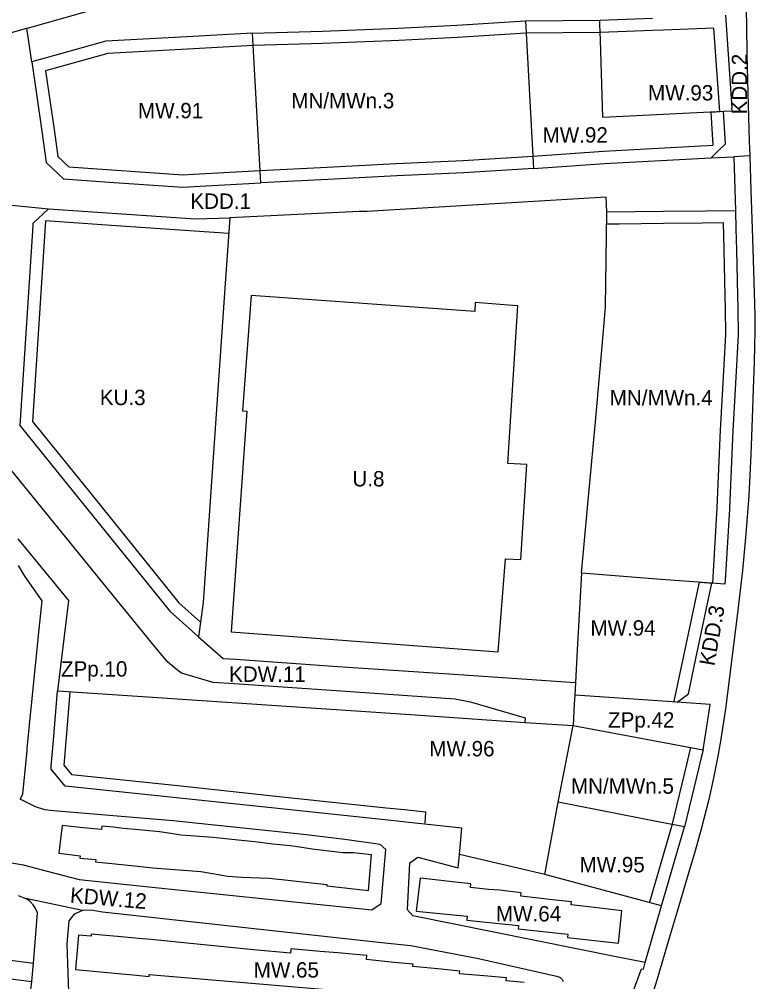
# Model space of a CAD drawing. Extents: x 7424434 to 7425898, y 5541432 to 5542659.
# Drawn here: x 7425584.1 to 7425823, y 5542027 to 5542339.7 of the extents above; entities that cross this region are included whole.
import ezdxf

# ---------------------------------------------------------------- set-up
doc = ezdxf.new("R2010")
doc.units = 0
for name, color, linetype in [('Default', 7, 'Continuous'), ('linie rozgraniczające', 7, 'Continuous'), ('nieprzekraczalne linie zabudowy', 7, 'Continuous'), ('obowiazujace linie zabudowy', 7, 'Continuous'), ('przeznaczenia terenów', 7, 'Continuous')]:
    doc.layers.add(name, color=color, linetype=linetype)

# ---------------------------------------------------------------- blocks, each defined once
blk = doc.blocks.new('POINT_DISPLAY')
at = {"layer": 'Default'}
blk.add_line((0, 0), (0, 0), dxfattribs=at)

msp = doc.modelspace()

# ---------------------------------------------------------------- linework, layer by layer
at = {"layer": 'linie rozgraniczające'}
for p, q in [((7425820.13, 5542347.32), (7425820.33, 5542337.89)), ((7425586.82, 5542336.84), (7425612.05, 5542343.91)), ((7425813.48, 5542341), (7425815.61, 5542310.78)), ((7425707.19, 5542336.79), (7425726.25, 5542337.79)), ((7425726.25, 5542337.79), (7425748.57, 5542339.2)), ((7425748.57, 5542339.2), (7425772.68, 5542339.36)), ((7425748.57, 5542339.2), (7425751.17, 5542291.2)), ((7425772.68, 5542339.36), (7425789.77, 5542340.05)), ((7425772.72, 5542338.14), (7425772.68, 5542339.36)), ((7425772.87, 5542332.92), (7425772.72, 5542338.14)), ((7425820.33, 5542337.89), (7425820.46, 5542328.05)), ((7425564.85, 5542330.75), (7425586.62, 5542336.78)), ((7425586.62, 5542336.78), (7425586.82, 5542336.84)), ((7425588.21, 5542325.83), (7425586.62, 5542336.78)), ((7425659.91, 5542335.18), (7425638.59, 5542334.02)), ((7425659.91, 5542335.18), (7425682.59, 5542335.83)), ((7425660.75, 5542319.63), (7425659.91, 5542335.18)), ((7425682.59, 5542335.83), (7425704.64, 5542336.69)), ((7425704.64, 5542336.69), (7425707.19, 5542336.79)), ((7425612.29, 5542332.58), (7425588.21, 5542325.83)), ((7425638.59, 5542334.02), (7425612.29, 5542332.58)), ((7425773.62, 5542307.87), (7425772.87, 5542332.92)), ((7425588.21, 5542325.83), (7425591.48, 5542303.35)), ((7425820.46, 5542328.05), (7425820.72, 5542315.79)), ((7425662.55, 5542286.57), (7425660.75, 5542319.63)), ((7425820.72, 5542315.79), (7425821.24, 5542300.09)), ((7425773.62, 5542307.87), (7425812.82, 5542309.79)), ((7425812.82, 5542309.79), (7425815.67, 5542309.93)), ((7425813.48, 5542299.23), (7425812.82, 5542309.79)), ((7425815.67, 5542309.93), (7425815.61, 5542310.78)), ((7425591.48, 5542303.35), (7425592.87, 5542293.15)), ((7425821.24, 5542300.09), (7425821.39, 5542295.38)), ((7425810.87, 5542296.71), (7425813.48, 5542299.23)), ((7425774.17, 5542292.81), (7425808.75, 5542294.66)), ((7425808.75, 5542294.66), (7425816.17, 5542295.05)), ((7425808.75, 5542294.66), (7425808.8, 5542294.71)), ((7425808.8, 5542294.71), (7425810.87, 5542296.71)), ((7425821.39, 5542295.38), (7425816.17, 5542295.05)), ((7425816.17, 5542295.05), (7425816.77, 5542277.58)), ((7425821.39, 5542295.38), (7425821.76, 5542284.09)), ((7425592.87, 5542293.15), (7425598.54, 5542287.85)), ((7425751.17, 5542291.2), (7425728.48, 5542289.81)), ((7425751.17, 5542291.2), (7425774.17, 5542292.81)), ((7425598.54, 5542287.85), (7425614.94, 5542286.72)), ((7425684.3, 5542287.64), (7425662.55, 5542286.57)), ((7425706.78, 5542288.82), (7425684.3, 5542287.64)), ((7425728.48, 5542289.81), (7425706.78, 5542288.82)), ((7425614.94, 5542286.72), (7425637.29, 5542285.18)), ((7425637.29, 5542285.18), (7425640.94, 5542285.38)), ((7425640.94, 5542285.38), (7425662.55, 5542286.57)), ((7425774.74, 5542281.86), (7425697.06, 5542277.29)), ((7425774.98, 5542277.14), (7425774.74, 5542281.86)), ((7425821.76, 5542284.09), (7425822.16, 5542271.74)), ((7425577.28, 5542279.74), (7425593.66, 5542278.16)), ((7425593.66, 5542278.16), (7425588.52, 5542273.39)), ((7425593.66, 5542278.16), (7425614.29, 5542276.74)), ((7425614.29, 5542276.74), (7425641.42, 5542274.87)), ((7425641.42, 5542274.87), (7425652.53, 5542275.14)), ((7425652.53, 5542275.14), (7425650.93, 5542252.36)), ((7425694.51, 5542277.23), (7425652.53, 5542275.14)), ((7425697.06, 5542277.29), (7425694.51, 5542277.23)), ((7425774.56, 5542246.29), (7425774.98, 5542277.14)), ((7425774.98, 5542277.14), (7425793.34, 5542277.33)), ((7425793.34, 5542277.33), (7425807.13, 5542277.48)), ((7425807.13, 5542277.48), (7425816.77, 5542277.58)), ((7425816.77, 5542277.58), (7425816.89, 5542271.62)), ((7425588.5, 5542272.6), (7425584.37, 5542207.73)), ((7425588.52, 5542273.14), (7425588.5, 5542272.6)), ((7425588.52, 5542273.39), (7425588.52, 5542273.14)), ((7425816.89, 5542271.62), (7425817.03, 5542264.73)), ((7425822.16, 5542271.74), (7425822.61, 5542258.07)), ((7425817.03, 5542264.73), (7425817.43, 5542249.81)), ((7425822.61, 5542258.07), (7425823, 5542243.56)), ((7425650.93, 5542252.36), (7425648.25, 5542213.07)), ((7425817.43, 5542249.81), (7425817.53, 5542245.83)), ((7425773.93, 5542238.44), (7425774.56, 5542246.29)), ((7425817.53, 5542245.83), (7425817.6, 5542237.21)), ((7425823, 5542243.56), (7425823, 5542238.32)), ((7425771.36, 5542210.15), (7425773.93, 5542238.44)), ((7425823, 5542238.32), (7425822.77, 5542228.43)), ((7425817.6, 5542237.21), (7425816.94, 5542225.31)), ((7425822.77, 5542228.43), (7425822.46, 5542219.66)), ((7425816.94, 5542225.31), (7425815.87, 5542205.98)), ((7425822.46, 5542219.66), (7425822.13, 5542210.05)), ((7425648.25, 5542213.07), (7425643.82, 5542150.17)), ((7425769.1, 5542185.66), (7425771.36, 5542210.15)), ((7425822.13, 5542210.05), (7425821.72, 5542198.33)), ((7425584.37, 5542207.73), (7425603.81, 5542183.61)), ((7425815.87, 5542205.98), (7425814.78, 5542180.74)), ((7425821.72, 5542198.33), (7425821.04, 5542184.91)), ((7425613.28, 5542154.25), (7425578.96, 5542196.49)), ((7425766.75, 5542159.72), (7425769, 5542184.59)), ((7425769, 5542184.59), (7425769.1, 5542185.66)), ((7425821.04, 5542184.91), (7425820.15, 5542172.55)), ((7425603.81, 5542183.61), (7425633.03, 5542147.35)), ((7425814.76, 5542180.54), (7425813.51, 5542159.13)), ((7425814.78, 5542180.74), (7425814.76, 5542180.54)), ((7425820.15, 5542172.55), (7425819.04, 5542160.65)), ((7425583.73, 5542170.93), (7425600.13, 5542150.9)), ((7425586, 5542158.81), (7425583.91, 5542162.26)), ((7425766.75, 5542159.72), (7425765.3, 5542134.8)), ((7425792.66, 5542157.73), (7425766.75, 5542159.72)), ((7425819.04, 5542160.65), (7425817.34, 5542145.9)), ((7425591.53, 5542150.73), (7425586, 5542158.81)), ((7425809.05, 5542156.47), (7425792.66, 5542157.73)), ((7425803.89, 5542132.07), (7425809.05, 5542156.47)), ((7425813.33, 5542156.14), (7425809.05, 5542156.47)), ((7425813.51, 5542159.13), (7425813.33, 5542156.14)), ((7425627.01, 5542137.29), (7425613.28, 5542154.25)), ((7425590.6, 5542141.51), (7425591.53, 5542150.73)), ((7425600.13, 5542150.9), (7425596.58, 5542121.55)), ((7425643.82, 5542150.17), (7425642.38, 5542139.11)), ((7425633.03, 5542147.35), (7425642.38, 5542139.11)), ((7425817.34, 5542145.9), (7425813.47, 5542115.62)), ((7425586.74, 5542102.84), (7425590.6, 5542141.51)), ((7425642.38, 5542139.11), (7425650.38, 5542132.06)), ((7425632.21, 5542131.1), (7425627.01, 5542137.29)), ((7425765.3, 5542134.8), (7425764.74, 5542124.19)), ((7425634.59, 5542128.96), (7425632.21, 5542131.1)), ((7425650.38, 5542132.06), (7425654.45, 5542131.78)), ((7425654.45, 5542131.78), (7425687.59, 5542129.47)), ((7425801.44, 5542120.52), (7425803.89, 5542132.07)), ((7425636.88, 5542127.21), (7425634.59, 5542128.96)), ((7425687.59, 5542129.47), (7425726.94, 5542126.79)), ((7425647.12, 5542124.26), (7425636.88, 5542127.21)), ((7425726.94, 5542126.79), (7425764.74, 5542124.19)), ((7425653.9, 5542123.8), (7425647.12, 5542124.26)), ((7425687.04, 5542121.49), (7425653.9, 5542123.8)), ((7425764.74, 5542124.19), (7425764.52, 5542120.11)), ((7425595.24, 5542105.36), (7425596.58, 5542121.55)), ((7425596.58, 5542121.55), (7425625.77, 5542119.58)), ((7425625.77, 5542119.58), (7425711.22, 5542113.8)), ((7425725.67, 5542118.84), (7425687.04, 5542121.49)), ((7425731.17, 5542117.68), (7425725.67, 5542118.84)), ((7425764.52, 5542120.11), (7425764.36, 5542117.24)), ((7425764.52, 5542120.11), (7425764.63, 5542120.1)), ((7425797.86, 5542117.81), (7425764.63, 5542120.1)), ((7425797.86, 5542117.81), (7425801.44, 5542120.52)), ((7425748.5, 5542112.62), (7425731.17, 5542117.68)), ((7425764.36, 5542117.24), (7425763.99, 5542110.23)), ((7425808.57, 5542117.07), (7425797.86, 5542117.81)), ((7425807.88, 5542112.77), (7425808.57, 5542117.07)), ((7425813.47, 5542115.62), (7425812.68, 5542110.09)), ((7425711.22, 5542113.8), (7425748.41, 5542111.28)), ((7425748.41, 5542111.28), (7425748.5, 5542112.62)), ((7425806.2, 5542102.36), (7425807.88, 5542112.77)), ((7425759.2, 5542085.34), (7425763.99, 5542110.23)), ((7425763.99, 5542110.23), (7425802.83, 5542102.99)), ((7425812.68, 5542110.09), (7425811.9, 5542105.19)), ((7425594.55, 5542097.07), (7425595.24, 5542105.36)), ((7425802.83, 5542102.99), (7425806.2, 5542102.36)), ((7425811.9, 5542105.19), (7425810.92, 5542099.72)), ((7425585.29, 5542087.99), (7425586.67, 5542102.14)), ((7425586.67, 5542102.14), (7425586.74, 5542102.84)), ((7425806.2, 5542102.36), (7425805.5, 5542099.47)), ((7425594.47, 5542096.06), (7425594.55, 5542097.07)), ((7425804.93, 5542097.11), (7425804.7, 5542096.15)), ((7425805.5, 5542099.47), (7425804.93, 5542097.11)), ((7425810.92, 5542099.72), (7425809.53, 5542092.75)), ((7425599.07, 5542090.55), (7425594.47, 5542096.06)), ((7425804.7, 5542096.15), (7425800.15, 5542077.33)), ((7425635.22, 5542086.73), (7425599.07, 5542090.55)), ((7425809.53, 5542092.75), (7425808.08, 5542086.24)), ((7425584.47, 5542086.32), (7425585.29, 5542087.99)), ((7425589.39, 5542083.87), (7425584.47, 5542086.32)), ((7425669.06, 5542083.15), (7425635.22, 5542086.73)), ((7425754.82, 5542061.82), (7425759.2, 5542085.34)), ((7425792.2, 5542078.88), (7425759.2, 5542085.34)), ((7425808.08, 5542086.24), (7425805.64, 5542076.59)), ((7425592.41, 5542082.87), (7425589.39, 5542083.87)), ((7425595.27, 5542082.52), (7425592.41, 5542082.87)), ((7425634.13, 5542079.3), (7425595.27, 5542082.52)), ((7425702.89, 5542079.56), (7425669.06, 5542083.15)), ((7425676.49, 5542074.85), (7425634.13, 5542079.3)), ((7425708.86, 5542078.94), (7425702.89, 5542079.56)), ((7425709.65, 5542078.86), (7425708.86, 5542078.94)), ((7425727.88, 5542076.93), (7425709.65, 5542078.86)), ((7425800.15, 5542077.33), (7425792.2, 5542078.88)), ((7425689.91, 5542073.26), (7425676.49, 5542074.85)), ((7425727.08, 5542068.35), (7425727.88, 5542076.93)), ((7425792.77, 5542051.66), (7425800.15, 5542077.33)), ((7425805.64, 5542076.59), (7425803.64, 5542069.53)), ((7425701.38, 5542071.55), (7425689.91, 5542073.26)), ((7425703.14, 5542070.02), (7425701.38, 5542071.55)), ((7425701.7, 5542052.4), (7425703.14, 5542070.02)), ((7425803.64, 5542069.53), (7425800.83, 5542060.07)), ((7425579.75, 5542065.95), (7425585.36, 5542064.96)), ((7425710.26, 5542050.35), (7425710.98, 5542065.67)), ((7425710.98, 5542065.67), (7425713.57, 5542067.5)), ((7425713.57, 5542067.5), (7425726.67, 5542063.97)), ((7425726.67, 5542063.97), (7425727.08, 5542068.35)), ((7425754.82, 5542061.82), (7425727.08, 5542068.35)), ((7425585.36, 5542064.96), (7425595.27, 5542062.35)), ((7425595.27, 5542062.35), (7425603.63, 5542060.22)), ((7425603.63, 5542060.22), (7425629.32, 5542057.5)), ((7425792.77, 5542051.66), (7425754.82, 5542061.82)), ((7425800.83, 5542060.07), (7425797.78, 5542049.81)), ((7425629.32, 5542057.5), (7425698.65, 5542050.34)), ((7425431.98, 5542052.97), (7425588.81, 5542033.02)), ((7425583.8, 5542054.97), (7425585.45, 5542054.36)), ((7425585.45, 5542054.36), (7425586.25, 5542054.02)), ((7425587.71, 5542053.06), (7425586.25, 5542054.02)), ((7425604.73, 5542050.18), (7425586.25, 5542054.02)), ((7425588.64, 5542051.99), (7425587.71, 5542053.06)), ((7425589.15, 5542051.26), (7425588.64, 5542051.99)), ((7425590.04, 5542049.36), (7425589.15, 5542051.26)), ((7425604.73, 5542050.18), (7425602, 5542048.97)), ((7425607.52, 5542050.31), (7425604.73, 5542050.18)), ((7425611.21, 5542049.61), (7425607.52, 5542050.31)), ((7425698.65, 5542050.34), (7425701.7, 5542052.4)), ((7425711.97, 5542048.47), (7425710.26, 5542050.35)), ((7425787.46, 5542033.22), (7425792.77, 5542051.66)), ((7425797.78, 5542049.81), (7425795.2, 5542041.13)), ((7425432, 5542046.92), (7425588.17, 5542027.05)), ((7425588.81, 5542033.02), (7425590.04, 5542049.36)), ((7425600.21, 5542046.81), (7425599.54, 5542039.18)), ((7425602, 5542048.97), (7425600.21, 5542046.81)), ((7425703.88, 5542039.43), (7425611.21, 5542049.61)), ((7425777.95, 5542035.14), (7425711.97, 5542048.47)), ((7425795.2, 5542041.13), (7425791.17, 5542027.57)), ((7425599.54, 5542039.18), (7425600.19, 5542020.57)), ((7425711.26, 5542038.62), (7425703.88, 5542039.43)), ((7425733.26, 5542034.43), (7425711.26, 5542038.62)), ((7425759.21, 5542028.6), (7425733.26, 5542034.43)), ((7425787.46, 5542033.22), (7425777.95, 5542035.14)), ((7425588.17, 5542027.05), (7425588.81, 5542033.02)), ((7425783.55, 5542023.81), (7425786.17, 5542031.23)), ((7425786.17, 5542031.23), (7425786.85, 5542031.09)), ((7425786.85, 5542031.09), (7425787.46, 5542033.22)), ((7425759.91, 5542028.29), (7425759.21, 5542028.6)), ((7425760.58, 5542027.6), (7425759.91, 5542028.29)), ((7425586.8, 5542014.33), (7425588.17, 5542027.05)), ((7425760.89, 5542026.95), (7425760.58, 5542027.6)), ((7425791.17, 5542027.57), (7425787.89, 5542017.02))]:
    msp.add_line(p, q, dxfattribs=at)
msp.add_lwpolyline([(7425748.41, 5542111.28), (7425763.99, 5542110.23), (7425763.99, 5542110.23)], dxfattribs=at)
at = {"layer": 'nieprzekraczalne linie zabudowy'}
for points in [[(7425809.76, 5542336.85), (7425793.38, 5542336.19), (7425789.93, 5542336.05), (7425772.77, 5542335.36), (7425748.71, 5542335.2), (7425726.48, 5542333.8), (7425707.37, 5542332.79), (7425704.8, 5542332.69), (7425682.73, 5542331.83), (7425660.08, 5542331.18), (7425638.81, 5542330.02), (7425612.95, 5542328.61), (7425592.67, 5542322.93), (7425595.44, 5542303.91), (7425596.64, 5542295.1), (7425600.23, 5542291.74), (7425637.32, 5542289.19), (7425640.72, 5542289.37), (7425662.34, 5542290.56), (7425684.1, 5542291.63), (7425706.58, 5542292.82), (7425728.27, 5542293.8), (7425750.91, 5542295.19), (7425773.92, 5542296.8), (7425809.48, 5542298.75), (7425808.83, 5542309.55), (7425811.65, 5542309.73), (7425809.76, 5542336.85)], [(7425652.18, 5542270.12), (7425614.01, 5542272.75), (7425592.61, 5542274.23), (7425588.46, 5542209.03), (7425606.92, 5542186.12), (7425635.93, 5542150.13), (7425643.02, 5542143.87)], [(7425796.86, 5542118.2), (7425799.98, 5542132.9), (7425804.19, 5542152.83), (7425805.03, 5542156.78), (7425809.35, 5542156.45), (7425809.58, 5542160.44), (7425810.77, 5542180.86), (7425810.79, 5542181.03), (7425811.87, 5542206.18), (7425812.95, 5542225.53), (7425813.6, 5542237.3), (7425813.53, 5542245.76), (7425813.43, 5542249.71), (7425813.03, 5542264.64), (7425812.94, 5542269.33), (7425812.85, 5542273.54), (7425806.04, 5542273.47), (7425793.38, 5542273.33), (7425778.93, 5542273.18), (7425774.93, 5542273.14)], [(7425656.69, 5542212.51), (7425658.07, 5542212.41)], [(7425600.57, 5542121.22), (7425599.23, 5542105.03), (7425598.59, 5542097.37), (7425601.1, 5542094.35), (7425635.64, 5542090.71), (7425669.48, 5542087.13), (7425703.31, 5542083.54), (7425709.28, 5542082.92), (7425716.11, 5542082.2), (7425715.85, 5542078.56)], [(7425788.98, 5542052.97), (7425796.28, 5542078.35), (7425800.93, 5542097.57), (7425801.61, 5542100.41), (7425802.28, 5542103.15)]]:
    msp.add_lwpolyline(points, dxfattribs=at)
msp.add_lwpolyline([(7425656.69, 5542212.51), (7425658.07, 5542212.41), (7425652.94, 5542140.72), (7425739.66, 5542134.2), (7425742.07, 5542164.45), (7425747.01, 5542164.14), (7425748.96, 5542195.02), (7425742.8, 5542195.41), (7425746.04, 5542246.65), (7425743.03, 5542246.86), (7425732.25, 5542247.73), (7425732.06, 5542244.72), (7425659.47, 5542250)], close=True, dxfattribs=at)
at = {"layer": 'obowiazujace linie zabudowy'}
for points in [[(7425603.88, 5542067.87), (7425603.83, 5542067.12), (7425608.96, 5542066.73), (7425608.9, 5542065.94), (7425622.7, 5542064.54), (7425627.57, 5542064.04), (7425643.08, 5542062.87), (7425651.88, 5542061.32), (7425656.46, 5542060.98), (7425665.3, 5542060.63), (7425670.35, 5542060.08), (7425675.13, 5542059.55), (7425684.03, 5542058.58), (7425683.99, 5542058.15), (7425697.6, 5542056.65), (7425698.58, 5542068.21), (7425692.66, 5542068.9), (7425689.2, 5542068.89), (7425679.27, 5542070.11), (7425675.96, 5542070.64), (7425672.2, 5542071.16), (7425666.48, 5542071.73), (7425660.52, 5542072.41), (7425653.22, 5542073.24), (7425647.08, 5542073.87), (7425639.78, 5542074.37), (7425636.62, 5542074.62), (7425633.39, 5542075.21), (7425629.67, 5542075.66), (7425624.14, 5542076.21), (7425618, 5542076.75), (7425614.72, 5542077.21), (7425610.94, 5542077.6), (7425610.82, 5542076.42), (7425604.86, 5542077.04), (7425598.06, 5542077.77), (7425596.98, 5542068.78)], [(7425713.07, 5542049.96), (7425729.57, 5542048.27), (7425729.46, 5542047.03), (7425746.25, 5542045.27), (7425746.13, 5542044.14), (7425762.28, 5542042.46), (7425762.17, 5542041.33), (7425778.75, 5542039.51), (7425779.84, 5542050), (7425772.64, 5542050.88), (7425769, 5542051.29), (7425763.36, 5542051.94), (7425763.48, 5542052.94), (7425756.34, 5542053.77), (7425752.76, 5542054.18), (7425747.03, 5542054.84), (7425747.16, 5542055.92), (7425740.15, 5542056.74), (7425736.52, 5542056.99), (7425730.65, 5542057.62), (7425730.79, 5542058.84), (7425723.84, 5542059.6), (7425720.22, 5542059.97), (7425714.29, 5542060.61)]]:
    msp.add_lwpolyline(points, close=True, dxfattribs=at)
msp.add_lwpolyline([(7425748.14, 5542026.8), (7425742.29, 5542027.3), (7425742.37, 5542028.3), (7425736.3, 5542028.82), (7425727.13, 5542029.61), (7425727.21, 5542030.47), (7425721.18, 5542031.06), (7425711.98, 5542031.96), (7425712.05, 5542032.7), (7425705.9, 5542033.3), (7425696.88, 5542034.18), (7425697.01, 5542035.51), (7425687.59, 5542036.35), (7425681.82, 5542036.85), (7425672.33, 5542037.69), (7425672.2, 5542036.24), (7425660.25, 5542037.39), (7425626.82, 5542040.71), (7425622.84, 5542041.09), (7425617.27, 5542041.55), (7425611.05, 5542042.15), (7425607.54, 5542042.49), (7425607.47, 5542041.79), (7425603.35, 5542042.16), (7425602.36, 5542030.94), (7425616.21, 5542029.71), (7425621.1, 5542029.25), (7425626.3, 5542028.73), (7425626.34, 5542029.32), (7425710.79, 5542022.16)], dxfattribs=at)

# ---------------------------------------------------------------- block references
at = {"layer": 'nieprzekraczalne linie zabudowy', "xscale": 0.01, "yscale": 0.01}
for p in [(7425748.96, 5542195.02), (7425747.01, 5542164.14)]:
    msp.add_blockref('POINT_DISPLAY', p, dxfattribs=at)

# ---------------------------------------------------------------- texts
at = {"layer": 'przeznaczenia terenów'}
for s, rotation, p in [('KDD.2', 90, (7425820.54, 5542308.79)), ('KDD.3', 80, (7425809.85, 5542129.39)), ('KDW.12', 355.1061, (7425600.49, 5542052.72))]:
    msp.add_text(s, height=5, rotation=rotation, dxfattribs=at).set_placement(p)
for s, p in [('MN/MWn.3', (7425672.5, 5542310.76)), ('MW.93', (7425788.36, 5542313.32)), ('MW.91', (7425622.71, 5542307.53)), ('MW.92', (7425754.11, 5542299.63)), ('KDD.1', (7425639.71, 5542278.11)), ('KU.3', (7425610.31, 5542214.34)), ('MN/MWn.4', (7425775.91, 5542214.23)), ('U.8', (7425692.34, 5542187.92)), ('MW.94', (7425769.64, 5542139.45)), ('ZPp.10', (7425597.69, 5542126.13)), ('KDW.11', (7425652.29, 5542124.43)), ('ZPp.42', (7425775.35, 5542109.58)), ('MW.96', (7425717.32, 5542100.23)), ('MN/MWn.5', (7425763.32, 5542088.09)), ('MW.95', (7425766.1, 5542062.54)), ('MW.64', (7425738.96, 5542046.6)), ('MW.65', (7425660.29, 5542028.35))]:
    msp.add_text(s, height=5, dxfattribs=at).set_placement(p)

doc.saveas('drawing.dxf')
